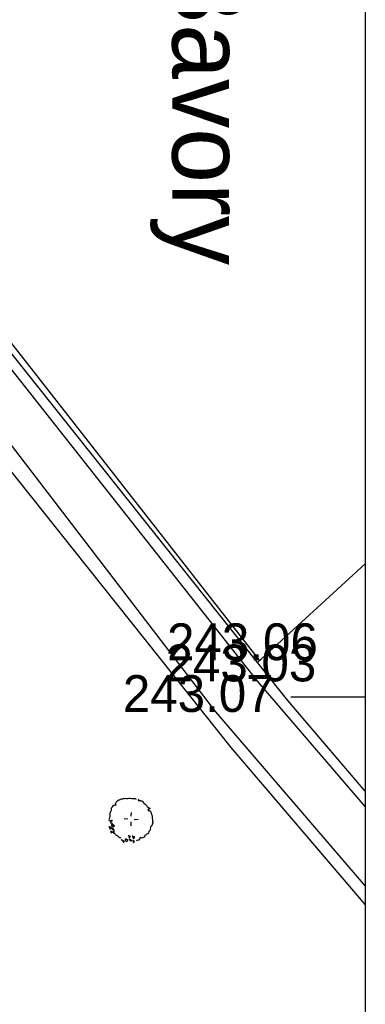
# Model space of a CAD drawing. Extents: x -601754 to -601440, y -1201912 to -1200862.
# Drawn here: x -601473.3 to -601454.6, y -1201719 to -1201665.6 of the extents above; entities that cross this region are included whole.
import ezdxf

# ---------------------------------------------------------------- set-up
doc = ezdxf.new("R2010")
doc.units = 0
for name, color, linetype in [('Hranice parcel', 7, 'Continuous'), ('u_hrany', 7, 'Continuous'), ('u_popis katastru', 7, 'Continuous'), ('u_vysadba', 7, 'Continuous'), ('u_vyska', 7, 'Continuous'), ('x_rám', 7, 'Continuous')]:
    doc.layers.add(name, color=color, linetype=linetype)

msp = doc.modelspace()

# ---------------------------------------------------------------- linework, layer by layer
at = {"layer": 'Hranice parcel'}
msp.add_line((-601454.585, -1201695.12), (-601460.43, -1201700.48), dxfattribs=at)
for points in [[(-601518.5, -1201574.62), (-601510.22, -1201581.07), (-601510.94, -1201612.53), (-601510.72, -1201619.53), (-601510.05, -1201624.75), (-601508.24, -1201633.75), (-601505.86, -1201640.82), (-601502.47, -1201648.58), (-601498.5, -1201656.04), (-601493.62, -1201663.46), (-601488.75, -1201670.45), (-601479.72, -1201682.69), (-601461.88, -1201705.09), (-601454.585, -1201713.629)], [(-601460.43, -1201700.48), (-601476.54, -1201680.26), (-601485.5, -1201668.12), (-601490.31, -1201661.22), (-601495.06, -1201653.99), (-601498.9, -1201646.76), (-601502.13, -1201639.37), (-601504.35, -1201632.81), (-601505.66, -1201626.3)], [(-601454.585, -1201707.465), (-601458.79, -1201702.54), (-601460.43, -1201700.48)]]:
    msp.add_lwpolyline(points, dxfattribs=at)
at = {"layer": 'u_hrany'}
for points in [[(-601460.33, -1201700.35), (-601477.02, -1201679.01), (-601490.59, -1201659.41), (-601493.47, -1201654.35), (-601500.4, -1201641.28), (-601502.56, -1201635.52), (-601504.77, -1201626.02), (-601500.77, -1201618.77)], [(-601454.585, -1201708.29), (-601460.41, -1201701.5), (-601476.94, -1201680.56), (-601485.91, -1201668.41), (-601495.49, -1201654.25), (-601502.92, -1201639.69), (-601504.84, -1201632.93)], [(-601507.17, -1201633.88), (-601501.63, -1201648), (-601497.69, -1201655.55), (-601488, -1201669.96), (-601478.86, -1201682.08), (-601462.72, -1201703.16), (-601454.585, -1201712.627)]]:
    msp.add_lwpolyline(points, dxfattribs=at)
at = {"layer": 'u_vysadba'}
for points in [[(-601468.287, -1201708.283), (-601468.285, -1201708.253), (-601468.225, -1201708.227), (-601468.195, -1201708.214), (-601468.165, -1201708.201), (-601468.136, -1201708.203), (-601468.107, -1201708.204), (-601468.12, -1201708.174), (-601468.133, -1201708.144), (-601468.116, -1201708.101), (-601468.099, -1201708.058), (-601468.068, -1201708.016), (-601468.037, -1201707.988), (-601468.006, -1201707.961), (-601467.961, -1201707.934), (-601467.917, -1201707.936), (-601467.886, -1201707.908), (-601467.812, -1201707.883), (-601467.753, -1201707.872), (-601467.708, -1201707.859), (-601467.65, -1201707.862), (-601467.605, -1201707.85), (-601467.561, -1201707.852), (-601467.488, -1201707.856), (-601467.415, -1201707.846), (-601467.342, -1201707.849), (-601467.254, -1201707.854), (-601467.166, -1201707.859), (-601467.093, -1201707.863), (-601467.05, -1201707.879), (-601467.022, -1201707.896)], [(-601466.875, -1201707.889), (-601466.891, -1201707.917), (-601466.893, -1201707.946), (-601466.909, -1201707.975), (-601466.864, -1201707.962), (-601466.835, -1201707.964), (-601466.806, -1201707.966), (-601466.763, -1201707.982), (-601466.719, -1201707.985), (-601466.677, -1201708.016), (-601466.649, -1201708.047), (-601466.622, -1201708.092), (-601466.58, -1201708.124), (-601466.524, -1201708.171), (-601466.482, -1201708.217), (-601466.455, -1201708.248), (-601466.414, -1201708.308), (-601466.357, -1201708.341), (-601466.315, -1201708.372), (-601466.272, -1201708.389), (-601466.273, -1201708.418)], [(-601468.287, -1201708.283), (-601468.288, -1201708.297), (-601468.334, -1201708.339), (-601468.365, -1201708.366), (-601468.367, -1201708.41), (-601468.369, -1201708.454), (-601468.372, -1201708.512), (-601468.389, -1201708.555), (-601468.405, -1201708.584), (-601468.421, -1201708.612), (-601468.439, -1201708.67), (-601468.441, -1201708.699), (-601468.444, -1201708.758), (-601468.446, -1201708.801), (-601468.448, -1201708.831), (-601468.466, -1201708.903), (-601468.483, -1201708.946), (-601468.485, -1201708.99), (-601468.501, -1201709.018), (-601468.488, -1201709.048), (-601468.445, -1201709.065), (-601468.356, -1201709.04), (-601468.326, -1201709.027), (-601468.359, -1201709.084), (-601468.389, -1201709.112), (-601468.405, -1201709.14), (-601468.408, -1201709.184), (-601468.379, -1201709.186), (-601468.335, -1201709.188), (-601468.322, -1201709.218), (-601468.339, -1201709.261), (-601468.355, -1201709.289), (-601468.357, -1201709.333), (-601468.359, -1201709.377)], [(-601466.273, -1201708.418), (-601466.318, -1201708.431), (-601466.363, -1201708.443), (-601466.379, -1201708.471), (-601466.366, -1201708.501), (-601466.339, -1201708.547), (-601466.309, -1201708.534), (-601466.264, -1201708.521), (-601466.237, -1201708.552), (-601466.223, -1201708.582), (-601466.225, -1201708.611), (-601466.199, -1201708.671), (-601466.187, -1201708.716), (-601466.174, -1201708.76), (-601466.147, -1201708.806), (-601466.149, -1201708.835), (-601466.151, -1201708.879), (-601466.153, -1201708.908), (-601466.141, -1201708.952), (-601466.129, -1201709.012), (-601466.132, -1201709.07), (-601466.121, -1201709.129), (-601466.122, -1201709.158), (-601466.124, -1201709.188), (-601466.126, -1201709.231), (-601466.157, -1201709.259), (-601466.158, -1201709.288), (-601466.175, -1201709.331), (-601466.191, -1201709.36), (-601466.237, -1201709.401), (-601466.241, -1201709.46), (-601466.258, -1201709.517), (-601466.277, -1201709.59), (-601466.324, -1201709.646), (-601466.357, -1201709.717), (-601466.389, -1201709.774), (-601466.449, -1201709.8), (-601466.48, -1201709.828), (-601466.526, -1201709.869), (-601466.557, -1201709.912), (-601466.574, -1201709.955), (-601466.634, -1201709.981), (-601466.679, -1201709.993), (-601466.709, -1201710.006), (-601466.752, -1201709.989), (-601466.795, -1201709.972), (-601466.812, -1201710.015), (-601466.829, -1201710.073), (-601466.846, -1201710.116), (-601466.891, -1201710.128), (-601466.935, -1201710.126)], [(-601467.471, -1201708.976), (-601467.676, -1201708.965)], [(-601467.287, -1201708.824), (-601467.277, -1201708.62)], [(-601468.491, -1201709.37), (-601468.478, -1201709.4), (-601468.465, -1201709.445), (-601468.452, -1201709.475), (-601468.454, -1201709.504), (-601468.425, -1201709.52), (-601468.395, -1201709.492), (-601468.349, -1201709.451), (-601468.378, -1201709.449), (-601468.42, -1201709.418), (-601468.463, -1201709.401)], [(-601468.333, -1201709.437), (-601468.292, -1201709.483), (-601468.25, -1201709.529), (-601468.208, -1201709.561)], [(-601468.208, -1201709.561), (-601468.237, -1201709.559), (-601468.266, -1201709.558), (-601468.296, -1201709.556), (-601468.309, -1201709.526), (-601468.307, -1201709.497), (-601468.32, -1201709.467)], [(-601468.309, -1201709.248), (-601468.311, -1201709.292), (-601468.298, -1201709.322), (-601468.286, -1201709.366), (-601468.273, -1201709.396), (-601468.243, -1201709.398), (-601468.227, -1201709.369), (-601468.167, -1201709.343), (-601468.21, -1201709.326), (-601468.239, -1201709.31), (-601468.296, -1201709.278)], [(-601467.304, -1201709.131), (-601467.314, -1201709.335)], [(-601467.121, -1201708.994), (-601466.915, -1201708.99)], [(-601468.401, -1201709.609), (-601468.391, -1201709.698), (-601468.347, -1201709.7), (-601468.318, -1201709.701), (-601468.273, -1201709.689), (-601468.331, -1201709.671), (-601468.375, -1201709.669), (-601468.388, -1201709.639)], [(-601467.837, -1201710.02), (-601467.88, -1201710.003), (-601467.908, -1201709.987), (-601467.938, -1201709.985), (-601467.964, -1201709.94), (-601467.993, -1201709.924), (-601468.035, -1201709.892), (-601468.078, -1201709.875), (-601468.12, -1201709.829), (-601468.147, -1201709.798), (-601468.219, -1201709.765), (-601468.216, -1201709.721), (-601468.214, -1201709.678), (-601468.227, -1201709.648), (-601468.256, -1201709.631), (-601468.224, -1201709.589), (-601468.195, -1201709.591)], [(-601467.603, -1201710.032), (-601467.607, -1201710.105), (-601467.595, -1201710.15), (-601467.567, -1201710.18), (-601467.508, -1201710.169), (-601467.477, -1201710.141), (-601467.49, -1201710.111), (-601467.533, -1201710.094), (-601467.576, -1201710.077)], [(-601467.433, -1201709.851), (-601467.422, -1201709.924), (-601467.395, -1201709.97), (-601467.35, -1201709.957), (-601467.349, -1201709.928), (-601467.347, -1201709.899), (-601467.39, -1201709.882), (-601467.419, -1201709.866)], [(-601467.398, -1201710.028), (-601467.314, -1201710.106), (-601467.286, -1201710.122), (-601467.273, -1201710.152), (-601467.304, -1201710.18), (-601467.333, -1201710.178), (-601467.346, -1201710.148), (-601467.373, -1201710.103), (-601467.4, -1201710.072)], [(-601467.23, -1201709.891), (-601467.204, -1201709.951), (-601467.191, -1201709.995), (-601467.164, -1201710.026), (-601467.134, -1201710.013), (-601467.102, -1201709.971), (-601467.101, -1201709.941), (-601467.144, -1201709.939), (-601467.173, -1201709.923), (-601467.201, -1201709.907), (-601467.231, -1201709.905)], [(-601467.825, -1201710.079), (-601467.729, -1201710.201), (-601467.702, -1201710.246), (-601467.671, -1201710.204), (-601467.669, -1201710.175), (-601467.698, -1201710.159), (-601467.741, -1201710.142), (-601467.769, -1201710.126), (-601467.798, -1201710.11)], [(-601467.199, -1201710.141), (-601467.188, -1201710.215), (-601467.175, -1201710.245), (-601467.145, -1201710.232), (-601467.114, -1201710.19), (-601467.141, -1201710.159), (-601467.17, -1201710.143), (-601467.199, -1201710.141)], [(-601466.935, -1201710.126), (-601466.979, -1201710.138), (-601467.01, -1201710.166)]]:
    msp.add_lwpolyline(points, dxfattribs=at)
at = {"layer": 'x_rám'}
msp.add_line((-601454.585, -1201702.355), (-601458.625, -1201702.355), dxfattribs=at)
msp.add_lwpolyline([(-601454.585, -1200862.355), (-601454.585, -1201912.355), (-601751.585, -1201912.355), (-601751.585, -1200862.355)], close=True, dxfattribs=at)

# ---------------------------------------------------------------- texts
at = {"layer": 'u_popis katastru'}
msp.add_text('k.ú. Bavory', height=4, rotation=270, dxfattribs=at).set_placement((-601465.056, -1201652.136))
at = {"layer": 'u_vyska'}
for s, p in [('243.06', (-601465.34, -1201700.35)), ('243.03', (-601465.425, -1201701.5)), ('243.07', (-601467.74, -1201703.16))]:
    msp.add_text(s, height=2, dxfattribs=at).set_placement(p)

doc.saveas('drawing.dxf')
